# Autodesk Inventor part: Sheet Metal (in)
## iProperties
Shininess: 64.0
Length Units: 11272
Angle Units: 11279
Time Units: 11290
Mass Units: 11286
Length Display Precision: 3
Angle Display Precision: 2
Compacted: True
Part Number: Sheet Metal (in)
Document SubType Name: Sheet Metal
Created: 2002-07
Density: 0.0
Volumn: 0.0
Area: 0.0
PropertySet Name: Model Information
Control State: 0
Master: False
Checked Out: False
